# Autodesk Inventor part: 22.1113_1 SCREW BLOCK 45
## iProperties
Created: 2008-12
Part Number: 22.1113_1 SCREW BLOCK 45
Document SubType Name: Modeling
Designer: Administrator
Density: 1.06 g/cm^3
Material: ABS Plastic
Mass: 6.5432 g
Surface Area: 43.7545 cm^2
Volume: 6.17283 cm^3
Author: Administrator
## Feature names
1. Base1
